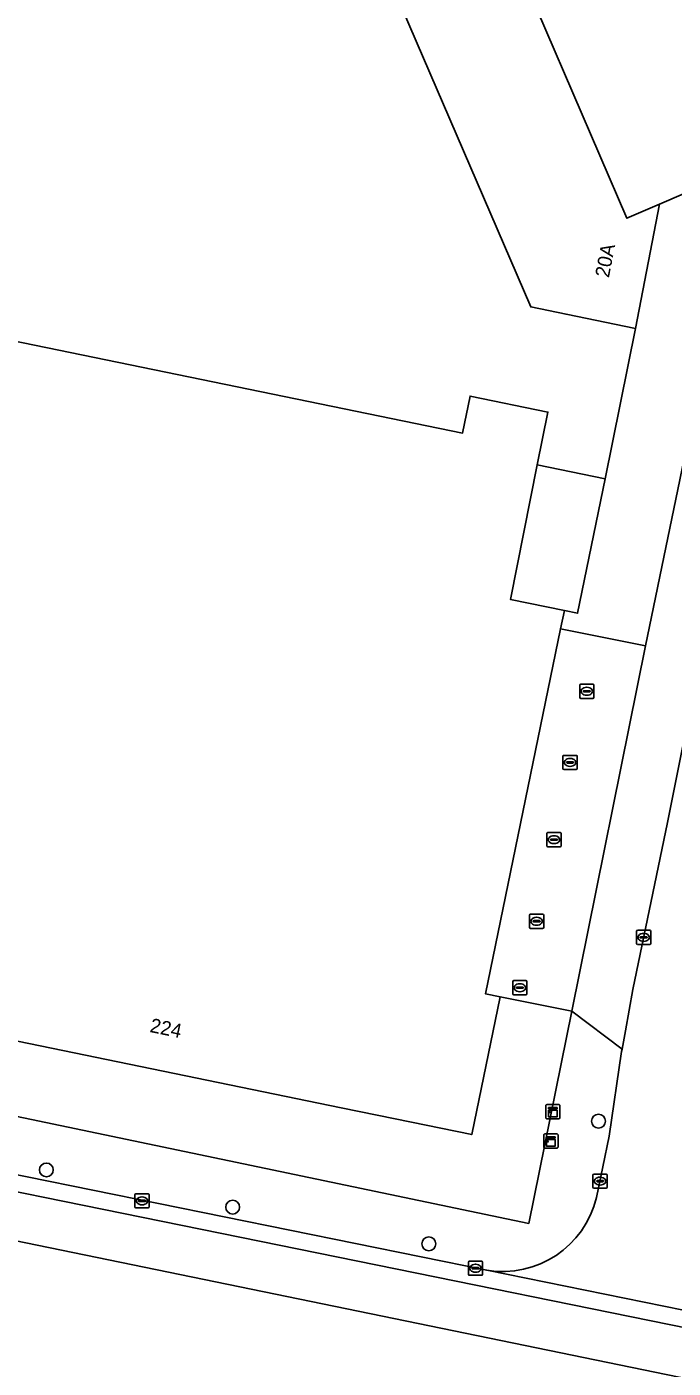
# Model space of a CAD drawing. Extents: x 158086 to 159499, y 382904 to 383981.
# Drawn here: x 158750.9 to 158796.6, y 382995.2 to 383089.9 of the extents above; entities that cross this region are included whole.
import ezdxf

# ---------------------------------------------------------------- set-up
doc = ezdxf.new("R2010")
doc.units = 0
for name, color, linetype in [('IMGEO_Boom', 7, 'Continuous'), ('IMGEO_Erf', 7, 'Continuous'), ('IMGEO_Kast', 7, 'Continuous'), ('IMGEO_Kolk', 7, 'Continuous'), ('IMGEO_Pand', 7, 'Continuous'), ('IMGEO_Pand_nummerreeks', 7, 'Continuous'), ('IMGEO_Parkeervlak_open', 7, 'Continuous'), ('IMGEO_Rijbaan_lokaal_gesloten', 7, 'Continuous'), ('IMGEO_Rijbaan_lokaal_open', 7, 'Continuous'), ('IMGEO_Voetpad_open', 7, 'Continuous')]:
    doc.layers.add(name, color=color, linetype=linetype)

msp = doc.modelspace()

# ---------------------------------------------------------------- linework, layer by layer
at = {"layer": 'IMGEO_Boom'}
for centre in [(158791.292, 383012.591), (158752.305, 383009.149), (158765.461, 383006.525), (158779.309, 383003.935)]:
    msp.add_circle(centre, 0.489, dxfattribs=at)
at = {"layer": 'IMGEO_Erf'}
msp.add_lwpolyline([(158776.04, 383094.375), (158775.916, 383095.471), (158771.783, 383094.846), (158761.199, 383093.782), (158748.475, 383092.503), (158750.034, 383078.044), (158747.892, 383067.794), (158729.739, 383071.533), (158724.841, 383072.542), (158724.899, 383072.159), (158725.782, 383066.336), (158726.467, 383061.823), (158731.365, 383060.817), (158746.016, 383057.807), (158748.125, 383068.073), (158781.694, 383061.178), (158782.229, 383063.783), (158787.714, 383062.657), (158786.952, 383058.944), (158791.767, 383057.954), (158793.9, 383068.563), (158789.002, 383069.567), (158786.505, 383070.079)], close=True, dxfattribs=at)
at = {"layer": 'IMGEO_Kast'}
for p, q in [((158787.57, 383012.839), (158787.57, 383013.68)), ((158787.57, 383013.68), (158787.57, 383012.839)), ((158787.645, 383013.764), (158788.486, 383013.764)), ((158788.486, 383013.764), (158787.645, 383013.764)), ((158788.57, 383013.689), (158788.57, 383012.848)), ((158788.57, 383012.848), (158788.57, 383013.689)), ((158788.495, 383012.764), (158787.654, 383012.764)), ((158787.654, 383012.764), (158788.495, 383012.764)), ((158787.434, 383010.767), (158787.434, 383011.608)), ((158787.434, 383011.608), (158787.434, 383010.767)), ((158787.509, 383011.692), (158788.35, 383011.692)), ((158788.35, 383011.692), (158787.509, 383011.692)), ((158788.434, 383011.617), (158788.434, 383010.776)), ((158788.434, 383010.776), (158788.434, 383011.617)), ((158788.359, 383010.692), (158787.518, 383010.692)), ((158787.518, 383010.692), (158788.359, 383010.692))]:
    msp.add_line(p, q, dxfattribs=at)
for points in [[(158787.765, 383013.554), (158788.365, 383013.554), (158788.365, 383013.469), (158787.765, 383013.469), (158787.765, 383013.554)], [(158787.765, 383013.379), (158788.365, 383013.379), (158788.365, 383012.89), (158787.765, 383012.89), (158787.765, 383013.379)], [(158787.629, 383011.482), (158788.229, 383011.482), (158788.229, 383011.397), (158787.629, 383011.397), (158787.629, 383011.482)], [(158787.629, 383011.307), (158788.229, 383011.307), (158788.229, 383010.818), (158787.629, 383010.818), (158787.629, 383011.307)]]:
    msp.add_lwpolyline(points, dxfattribs=at)
for centre in [(158787.849, 383013.228), (158787.713, 383011.156)]:
    msp.add_circle(centre, 0.0377, dxfattribs=at)
for centre, start, end in [((158787.648, 383013.686), 92.4484, 184.28452), ((158787.648, 383013.686), 92.4484, 184.28452), ((158788.492, 383013.686), 2.4484, 94.28452), ((158788.492, 383013.686), 2.4484, 94.28452), ((158787.648, 383012.842), 182.4484, 274.28452), ((158787.648, 383012.842), 182.4484, 274.28452), ((158788.492, 383012.842), 272.4484, 4.28452), ((158788.492, 383012.842), 272.4484, 4.28452), ((158787.512, 383011.614), 92.4484, 184.28452), ((158787.512, 383011.614), 92.4484, 184.28452), ((158788.356, 383011.614), 2.4484, 94.28452), ((158788.356, 383011.614), 2.4484, 94.28452), ((158787.512, 383010.77), 182.4484, 274.28452), ((158787.512, 383010.77), 182.4484, 274.28452), ((158788.356, 383010.77), 272.4484, 4.28452), ((158788.356, 383010.77), 272.4484, 4.28452)]:
    msp.add_arc(centre, 0.0779, start, end, dxfattribs=at)
at = {"layer": 'IMGEO_Kolk'}
for p, q in [((158789.963, 383042.518), (158789.963, 383043.37)), ((158790.038, 383043.444), (158790.89, 383043.444)), ((158790.222, 383042.938), (158790.222, 383042.95)), ((158790.66, 383042.901), (158790.262, 383042.901)), ((158790.265, 383042.987), (158790.663, 383042.987)), ((158790.451, 383043.224), (158790.476, 383043.224)), ((158790.706, 383042.95), (158790.706, 383042.938)), ((158790.964, 383043.37), (158790.964, 383042.518)), ((158790.89, 383042.444), (158790.038, 383042.444)), ((158790.474, 383042.664), (158790.449, 383042.664)), ((158788.784, 383037.495), (158788.784, 383038.347)), ((158788.859, 383038.421), (158789.711, 383038.421)), ((158789.086, 383037.964), (158789.484, 383037.964)), ((158789.272, 383038.201), (158789.297, 383038.201)), ((158789.785, 383038.347), (158789.785, 383037.495)), ((158789.711, 383037.421), (158788.859, 383037.421)), ((158789.043, 383037.915), (158789.043, 383037.927)), ((158789.481, 383037.878), (158789.083, 383037.878)), ((158789.295, 383037.641), (158789.27, 383037.641)), ((158789.527, 383037.927), (158789.527, 383037.915)), ((158787.646, 383032.04), (158787.646, 383032.892)), ((158787.721, 383032.966), (158788.573, 383032.966)), ((158787.905, 383032.46), (158787.905, 383032.472)), ((158788.343, 383032.423), (158787.945, 383032.423)), ((158787.948, 383032.509), (158788.346, 383032.509)), ((158788.134, 383032.746), (158788.159, 383032.746)), ((158788.389, 383032.472), (158788.389, 383032.46)), ((158788.647, 383032.892), (158788.647, 383032.04)), ((158788.573, 383031.966), (158787.721, 383031.966)), ((158788.157, 383032.186), (158788.132, 383032.186)), ((158786.42, 383026.28), (158786.42, 383027.132)), ((158786.495, 383027.206), (158787.347, 383027.206)), ((158786.679, 383026.7), (158786.679, 383026.712)), ((158787.117, 383026.663), (158786.719, 383026.663)), ((158786.722, 383026.749), (158787.12, 383026.749)), ((158786.908, 383026.986), (158786.933, 383026.986)), ((158787.163, 383026.712), (158787.163, 383026.7)), ((158787.421, 383027.132), (158787.421, 383026.28)), ((158787.347, 383026.206), (158786.495, 383026.206)), ((158786.931, 383026.426), (158786.906, 383026.426)), ((158793.982, 383025.142), (158793.982, 383025.994)), ((158794.057, 383026.068), (158794.909, 383026.068)), ((158794.47, 383025.848), (158794.495, 383025.848)), ((158794.983, 383025.994), (158794.983, 383025.142)), ((158794.909, 383025.068), (158794.057, 383025.068)), ((158794.241, 383025.562), (158794.241, 383025.574)), ((158794.679, 383025.525), (158794.281, 383025.525)), ((158794.284, 383025.611), (158794.682, 383025.611)), ((158794.493, 383025.288), (158794.468, 383025.288)), ((158794.725, 383025.574), (158794.725, 383025.562)), ((158785.24, 383021.588), (158785.24, 383022.44)), ((158785.315, 383022.514), (158786.167, 383022.514)), ((158785.499, 383022.008), (158785.499, 383022.02)), ((158785.937, 383021.971), (158785.539, 383021.971)), ((158785.542, 383022.057), (158785.94, 383022.057)), ((158785.728, 383022.294), (158785.753, 383022.294)), ((158785.983, 383022.02), (158785.983, 383022.008)), ((158786.241, 383022.44), (158786.241, 383021.588)), ((158786.167, 383021.514), (158785.315, 383021.514)), ((158785.751, 383021.734), (158785.726, 383021.734)), ((158790.902, 383007.931), (158790.902, 383008.783)), ((158790.977, 383008.857), (158791.829, 383008.857)), ((158791.39, 383008.637), (158791.415, 383008.637)), ((158791.903, 383008.783), (158791.903, 383007.931)), ((158791.829, 383007.857), (158790.977, 383007.857)), ((158791.161, 383008.351), (158791.161, 383008.363)), ((158791.599, 383008.314), (158791.201, 383008.314)), ((158791.204, 383008.4), (158791.602, 383008.4)), ((158791.413, 383008.077), (158791.388, 383008.077)), ((158791.645, 383008.363), (158791.645, 383008.351)), ((158758.558, 383006.539), (158758.558, 383007.391)), ((158758.633, 383007.465), (158759.485, 383007.465)), ((158758.817, 383006.959), (158758.817, 383006.971)), ((158759.255, 383006.922), (158758.857, 383006.922)), ((158758.86, 383007.008), (158759.258, 383007.008)), ((158759.069, 383006.685), (158759.044, 383006.685)), ((158759.046, 383007.245), (158759.071, 383007.245)), ((158759.301, 383006.971), (158759.301, 383006.959)), ((158759.559, 383007.391), (158759.559, 383006.539)), ((158759.485, 383006.465), (158758.633, 383006.465)), ((158782.105, 383001.782), (158782.105, 383002.634)), ((158782.18, 383002.708), (158783.032, 383002.708)), ((158782.364, 383002.202), (158782.364, 383002.214)), ((158782.802, 383002.165), (158782.404, 383002.165)), ((158782.407, 383002.251), (158782.805, 383002.251)), ((158782.593, 383002.488), (158782.618, 383002.488)), ((158782.848, 383002.214), (158782.848, 383002.202)), ((158783.106, 383002.634), (158783.106, 383001.782)), ((158783.032, 383001.708), (158782.18, 383001.708)), ((158782.616, 383001.928), (158782.591, 383001.928))]:
    msp.add_line(p, q, dxfattribs=at)
for points in [[(158789.963, 383042.518), (158789.963, 383043.37)], [(158790.038, 383043.444), (158790.89, 383043.444)], [(158790.964, 383043.37), (158790.964, 383042.518)], [(158790.89, 383042.444), (158790.038, 383042.444)], [(158788.784, 383037.495), (158788.784, 383038.347)], [(158788.859, 383038.421), (158789.711, 383038.421)], [(158789.785, 383038.347), (158789.785, 383037.495)], [(158789.711, 383037.421), (158788.859, 383037.421)], [(158787.646, 383032.04), (158787.646, 383032.892)], [(158787.721, 383032.966), (158788.573, 383032.966)], [(158788.647, 383032.892), (158788.647, 383032.04)], [(158788.573, 383031.966), (158787.721, 383031.966)], [(158786.42, 383026.28), (158786.42, 383027.132)], [(158786.495, 383027.206), (158787.347, 383027.206)], [(158787.421, 383027.132), (158787.421, 383026.28)], [(158787.347, 383026.206), (158786.495, 383026.206)], [(158793.982, 383025.142), (158793.982, 383025.994)], [(158794.057, 383026.068), (158794.909, 383026.068)], [(158794.983, 383025.994), (158794.983, 383025.142)], [(158794.909, 383025.068), (158794.057, 383025.068)], [(158785.24, 383021.588), (158785.24, 383022.44)], [(158785.315, 383022.514), (158786.167, 383022.514)], [(158786.241, 383022.44), (158786.241, 383021.588)], [(158786.167, 383021.514), (158785.315, 383021.514)], [(158790.902, 383007.931), (158790.902, 383008.783)], [(158790.977, 383008.857), (158791.829, 383008.857)], [(158791.903, 383008.783), (158791.903, 383007.931)], [(158791.829, 383007.857), (158790.977, 383007.857)], [(158758.558, 383006.539), (158758.558, 383007.391)], [(158758.633, 383007.465), (158759.485, 383007.465)], [(158759.559, 383007.391), (158759.559, 383006.539)], [(158759.485, 383006.465), (158758.633, 383006.465)], [(158782.105, 383001.782), (158782.105, 383002.634)], [(158782.18, 383002.708), (158783.032, 383002.708)], [(158783.106, 383002.634), (158783.106, 383001.782)], [(158783.032, 383001.708), (158782.18, 383001.708)]]:
    msp.add_lwpolyline(points, dxfattribs=at)
for centre, radius, start, end in [((158790.04, 383043.368), 0.0765, 91.55205, 178.44795), ((158790.04, 383043.368), 0.0765, 91.55205, 178.44795), ((158790.262, 383042.947), 0.0403, 85.87752, 175.75265), ((158790.259, 383042.937), 0.0366, 178.93798, 274.71019), ((158790.663, 383042.944), 0.043, 264.86636, 352.45326), ((158790.667, 383042.949), 0.0386, 1.73085, 96.63898), ((158790.888, 383043.368), 0.0765, 1.55205, 88.44795), ((158790.888, 383043.368), 0.0765, 1.55205, 88.44795), ((158790.04, 383042.52), 0.0765, 181.55205, 268.44795), ((158790.04, 383042.52), 0.0765, 181.55205, 268.44795), ((158790.888, 383042.52), 0.0765, 271.55205, 358.44795), ((158790.888, 383042.52), 0.0765, 271.55205, 358.44795), ((158788.861, 383038.345), 0.0765, 91.55205, 178.44795), ((158788.861, 383038.345), 0.0765, 91.55205, 178.44795), ((158789.083, 383037.924), 0.0403, 85.87752, 175.75265), ((158789.488, 383037.926), 0.0386, 1.73085, 96.63898), ((158789.709, 383038.345), 0.0765, 1.55205, 88.44795), ((158789.709, 383038.345), 0.0765, 1.55205, 88.44795), ((158788.861, 383037.497), 0.0765, 181.55205, 268.44795), ((158788.861, 383037.497), 0.0765, 181.55205, 268.44795), ((158789.08, 383037.914), 0.0366, 178.93798, 274.71019), ((158789.484, 383037.921), 0.043, 264.86636, 352.45326), ((158789.709, 383037.497), 0.0765, 271.55205, 358.44795), ((158789.709, 383037.497), 0.0765, 271.55205, 358.44795), ((158787.723, 383032.89), 0.0765, 91.55205, 178.44795), ((158787.723, 383032.89), 0.0765, 91.55205, 178.44795), ((158787.945, 383032.469), 0.0403, 85.87752, 175.75265), ((158787.942, 383032.459), 0.0366, 178.93798, 274.71019), ((158788.346, 383032.466), 0.043, 264.86636, 352.45326), ((158788.35, 383032.471), 0.0386, 1.73085, 96.63898), ((158788.571, 383032.89), 0.0765, 1.55205, 88.44795), ((158788.571, 383032.89), 0.0765, 1.55205, 88.44795), ((158787.723, 383032.042), 0.0765, 181.55205, 268.44795), ((158787.723, 383032.042), 0.0765, 181.55205, 268.44795), ((158788.571, 383032.042), 0.0765, 271.55205, 358.44795), ((158788.571, 383032.042), 0.0765, 271.55205, 358.44795), ((158786.497, 383027.13), 0.0765, 91.55205, 178.44795), ((158786.497, 383027.13), 0.0765, 91.55205, 178.44795), ((158786.719, 383026.709), 0.0403, 85.87752, 175.75265), ((158786.716, 383026.699), 0.0366, 178.93798, 274.71019), ((158787.12, 383026.706), 0.043, 264.86636, 352.45326), ((158787.124, 383026.711), 0.0386, 1.73085, 96.63898), ((158787.345, 383027.13), 0.0765, 1.55205, 88.44795), ((158787.345, 383027.13), 0.0765, 1.55205, 88.44795), ((158786.497, 383026.282), 0.0765, 181.55205, 268.44795), ((158786.497, 383026.282), 0.0765, 181.55205, 268.44795), ((158787.345, 383026.282), 0.0765, 271.55205, 358.44795), ((158787.345, 383026.282), 0.0765, 271.55205, 358.44795), ((158794.059, 383025.992), 0.0765, 91.55205, 178.44795), ((158794.059, 383025.992), 0.0765, 91.55205, 178.44795), ((158794.907, 383025.992), 0.0765, 1.55205, 88.44795), ((158794.907, 383025.992), 0.0765, 1.55205, 88.44795), ((158794.059, 383025.144), 0.0765, 181.55205, 268.44795), ((158794.059, 383025.144), 0.0765, 181.55205, 268.44795), ((158794.281, 383025.571), 0.0403, 85.87752, 175.75265), ((158794.278, 383025.561), 0.0366, 178.93798, 274.71019), ((158794.682, 383025.568), 0.043, 264.86636, 352.45326), ((158794.686, 383025.573), 0.0386, 1.73085, 96.63898), ((158794.907, 383025.144), 0.0765, 271.55205, 358.44795), ((158794.907, 383025.144), 0.0765, 271.55205, 358.44795), ((158785.317, 383022.438), 0.0765, 91.55205, 178.44795), ((158785.317, 383022.438), 0.0765, 91.55205, 178.44795), ((158785.539, 383022.017), 0.0403, 85.87752, 175.75265), ((158785.536, 383022.007), 0.0366, 178.93798, 274.71019), ((158785.94, 383022.014), 0.043, 264.86636, 352.45326), ((158785.944, 383022.019), 0.0386, 1.73085, 96.63898), ((158786.165, 383022.438), 0.0765, 1.55205, 88.44795), ((158786.165, 383022.438), 0.0765, 1.55205, 88.44795), ((158785.317, 383021.59), 0.0765, 181.55205, 268.44795), ((158785.317, 383021.59), 0.0765, 181.55205, 268.44795), ((158786.165, 383021.59), 0.0765, 271.55205, 358.44795), ((158786.165, 383021.59), 0.0765, 271.55205, 358.44795), ((158790.979, 383008.781), 0.0765, 91.55205, 178.44795), ((158790.979, 383008.781), 0.0765, 91.55205, 178.44795), ((158791.827, 383008.781), 0.0765, 1.55205, 88.44795), ((158791.827, 383008.781), 0.0765, 1.55205, 88.44795), ((158790.979, 383007.933), 0.0765, 181.55205, 268.44795), ((158790.979, 383007.933), 0.0765, 181.55205, 268.44795), ((158791.201, 383008.36), 0.0403, 85.87752, 175.75265), ((158791.198, 383008.35), 0.0366, 178.93798, 274.71019), ((158791.602, 383008.357), 0.043, 264.86636, 352.45326), ((158791.606, 383008.362), 0.0386, 1.73085, 96.63898), ((158791.827, 383007.933), 0.0765, 271.55205, 358.44795), ((158791.827, 383007.933), 0.0765, 271.55205, 358.44795), ((158758.635, 383007.389), 0.0765, 91.55205, 178.44795), ((158758.635, 383007.389), 0.0765, 91.55205, 178.44795), ((158758.857, 383006.968), 0.0403, 85.87752, 175.75265), ((158758.854, 383006.958), 0.0366, 178.93798, 274.71019), ((158759.258, 383006.965), 0.043, 264.86636, 352.45326), ((158759.262, 383006.97), 0.0386, 1.73085, 96.63898), ((158759.483, 383007.389), 0.0765, 1.55205, 88.44795), ((158759.483, 383007.389), 0.0765, 1.55205, 88.44795), ((158758.635, 383006.541), 0.0765, 181.55205, 268.44795), ((158758.635, 383006.541), 0.0765, 181.55205, 268.44795), ((158759.483, 383006.541), 0.0765, 271.55205, 358.44795), ((158759.483, 383006.541), 0.0765, 271.55205, 358.44795), ((158782.182, 383002.632), 0.0765, 91.55205, 178.44795), ((158782.182, 383002.632), 0.0765, 91.55205, 178.44795), ((158782.404, 383002.211), 0.0403, 85.87752, 175.75265), ((158782.401, 383002.201), 0.0366, 178.93798, 274.71019), ((158782.805, 383002.208), 0.043, 264.86636, 352.45326), ((158782.809, 383002.213), 0.0386, 1.73085, 96.63898), ((158783.03, 383002.632), 0.0765, 1.55205, 88.44795), ((158783.03, 383002.632), 0.0765, 1.55205, 88.44795), ((158782.182, 383001.784), 0.0765, 181.55205, 268.44795), ((158782.182, 383001.784), 0.0765, 181.55205, 268.44795), ((158783.03, 383001.784), 0.0765, 271.55205, 358.44795), ((158783.03, 383001.784), 0.0765, 271.55205, 358.44795)]:
    msp.add_arc(centre, radius, start, end, dxfattribs=at)
for centre, major_axis, ratio, start_param, end_param in [((158790.45, 383042.944), (-0.387, 0.002), 0.722429, 4.712389, 7.853982), ((158790.475, 383042.944), (-0.39, 0.002), 0.717154, 1.570796, 4.712389), ((158789.271, 383037.921), (-0.387, 0.002), 0.722429, 4.712389, 7.853982), ((158789.296, 383037.921), (-0.39, 0.002), 0.717154, 1.570796, 4.712389), ((158788.133, 383032.466), (-0.387, 0.002), 0.722429, 4.712389, 7.853982), ((158788.158, 383032.466), (-0.39, 0.002), 0.717154, 1.570796, 4.712389), ((158786.907, 383026.706), (-0.387, 0.002), 0.722429, 4.712389, 7.853982), ((158786.932, 383026.706), (-0.39, 0.002), 0.717154, 1.570796, 4.712389), ((158794.469, 383025.568), (-0.387, 0.002), 0.722429, 4.712389, 7.853982), ((158794.494, 383025.568), (-0.39, 0.002), 0.717154, 1.570796, 4.712389), ((158785.727, 383022.014), (-0.387, 0.002), 0.722429, 4.712389, 7.853982), ((158785.752, 383022.014), (-0.39, 0.002), 0.717154, 1.570796, 4.712389), ((158791.389, 383008.357), (-0.387, 0.002), 0.722429, 4.712389, 7.853982), ((158791.414, 383008.357), (-0.39, 0.002), 0.717154, 1.570796, 4.712389), ((158759.045, 383006.965), (-0.387, 0.002), 0.722429, 4.712389, 7.853982), ((158759.07, 383006.965), (-0.39, 0.002), 0.717154, 1.570796, 4.712389), ((158782.592, 383002.208), (-0.387, 0.002), 0.722429, 4.712389, 7.853982), ((158782.617, 383002.208), (-0.39, 0.002), 0.717154, 1.570796, 4.712389)]:
    msp.add_ellipse(centre, major_axis=major_axis, ratio=ratio, start_param=start_param, end_param=end_param, dxfattribs=at)
at = {"layer": 'IMGEO_Pand'}
for points in [[(158783.762, 383098.483), (158793.286, 383076.339), (158795.608, 383077.34), (158809.97, 383083.526), (158800.419, 383105.658)], [(158783.762, 383098.483), (158780.119, 383096.914), (158780.403, 383096.255), (158776.04, 383094.375), (158786.505, 383070.079), (158789.002, 383069.567), (158793.9, 383068.563), (158795.608, 383077.34), (158793.286, 383076.339)], [(158788.619, 383047.357), (158788.884, 383048.644), (158785.074, 383049.427), (158786.952, 383058.944), (158787.714, 383062.657), (158782.229, 383063.783), (158781.694, 383061.178), (158748.125, 383068.073), (158746.016, 383057.807), (158742.475, 383040.135), (158738.473, 383020.655), (158773.11, 383013.54), (158776.93, 383012.756), (158782.337, 383011.645), (158784.337, 383021.381), (158783.308, 383021.593)], [(158786.952, 383058.944), (158785.074, 383049.427), (158788.884, 383048.644), (158789.816, 383048.453), (158791.767, 383057.954)]]:
    msp.add_lwpolyline(points, close=True, dxfattribs=at)
at = {"layer": 'IMGEO_Parkeervlak_open'}
msp.add_lwpolyline([(158824.863, 383089.942), (158820.883, 383088.227), (158809.97, 383083.526), (158795.608, 383077.34), (158793.9, 383068.563), (158791.767, 383057.954), (158789.816, 383048.453), (158788.884, 383048.644), (158788.619, 383047.357), (158794.614, 383046.144), (158797.897, 383062.091)], dxfattribs=at)
msp.add_lwpolyline([(158718.129, 383019.64), (158786.37, 383005.371), (158789.4, 383020.358), (158784.337, 383021.381), (158782.337, 383011.645), (158776.93, 383012.756), (158773.11, 383013.54), (158738.473, 383020.655), (158723.962, 383023.636), (158721.552, 383024.131), (158718.839, 383024.688), (158718.64, 383023.433), (158718.89, 383023.383)], close=True, dxfattribs=at)
at = {"layer": 'IMGEO_Rijbaan_lokaal_gesloten'}
for points in [[(158679.693, 383023.234), (158679.452, 383022.056), (158697.779, 383018.312), (158715.258, 383014.844), (158734.231, 383010.854), (158803.226, 382996.829), (158803.465, 382998.005), (158797.296, 382999.254), (158783.406, 383002.064), (158737.006, 383011.496), (158734.474, 383012.029), (158714.12, 383016.31), (158712.107, 383016.722), (158698.338, 383019.425), (158698.015, 383019.488), (158696.902, 383019.718)], [(159136.507, 382922.214), (159138.468, 382926.137), (159138.724, 382926.621), (159136.836, 382927.421), (159134.281, 382928.299), (159031.685, 382949.921), (159015.031, 382953.509), (158803.226, 382996.829), (158734.231, 383010.854), (158715.258, 383014.844), (158697.779, 383018.312), (158679.452, 383022.056), (158678.787, 383018.803), (158704.703, 383013.476), (159041.051, 382944.343), (159049.485, 382942.388), (159115.477, 382927.089), (159115.479, 382927.089), (159130.494, 382923.938), (159134.522, 382922.866), (159135.209, 382922.515)]]:
    msp.add_lwpolyline(points, close=True, dxfattribs=at)
at = {"layer": 'IMGEO_Rijbaan_lokaal_open'}
for points in [[(158801.51, 383060.092), (158798.504, 383045.305), (158796.167, 383033.685), (158793.719, 383021.9), (158793.205, 383018.967), (158792.953, 383017.671), (158792.923, 383017.513), (158792.054, 383011.53), (158791.145, 383007.213)], [(158783.406, 383002.064), (158797.296, 382999.254), (158803.465, 382998.005)]]:
    msp.add_lwpolyline(points, dxfattribs=at)
msp.add_arc((158784.516, 383008.787), 6.814, 260.62793, 346.64621, dxfattribs=at)
at = {"layer": 'IMGEO_Voetpad_open'}
for points in [[(158797.897, 383062.091), (158794.614, 383046.144), (158789.4, 383020.358), (158792.953, 383017.671), (158793.205, 383018.967), (158793.719, 383021.9), (158796.167, 383033.685), (158798.504, 383045.305), (158801.51, 383060.092)], [(158791.145, 383007.213), (158792.054, 383011.53), (158792.923, 383017.513), (158792.953, 383017.671), (158789.4, 383020.358), (158786.37, 383005.371), (158718.129, 383019.64), (158718.02, 383019.106), (158715.656, 383019.635)], [(158712.107, 383016.722), (158714.12, 383016.31), (158734.474, 383012.029), (158737.006, 383011.496), (158783.406, 383002.064)]]:
    msp.add_lwpolyline(points, dxfattribs=at)
msp.add_lwpolyline([(158794.614, 383046.144), (158788.619, 383047.357), (158783.308, 383021.593), (158784.337, 383021.381), (158789.4, 383020.358)], close=True, dxfattribs=at)
msp.add_arc((158784.516, 383008.787), 6.814, 260.62793, 346.64621, dxfattribs=at)

# ---------------------------------------------------------------- texts
at = {"layer": 'IMGEO_Pand_nummerreeks'}
for s, rotation, p in [('20A', 78.9879, (158792.021, 383072.101)), ('224', 348.39188, (158759.561, 383018.896))]:
    msp.add_text(s, height=1, rotation=rotation, dxfattribs=at).set_placement(p)

doc.saveas('drawing.dxf')
